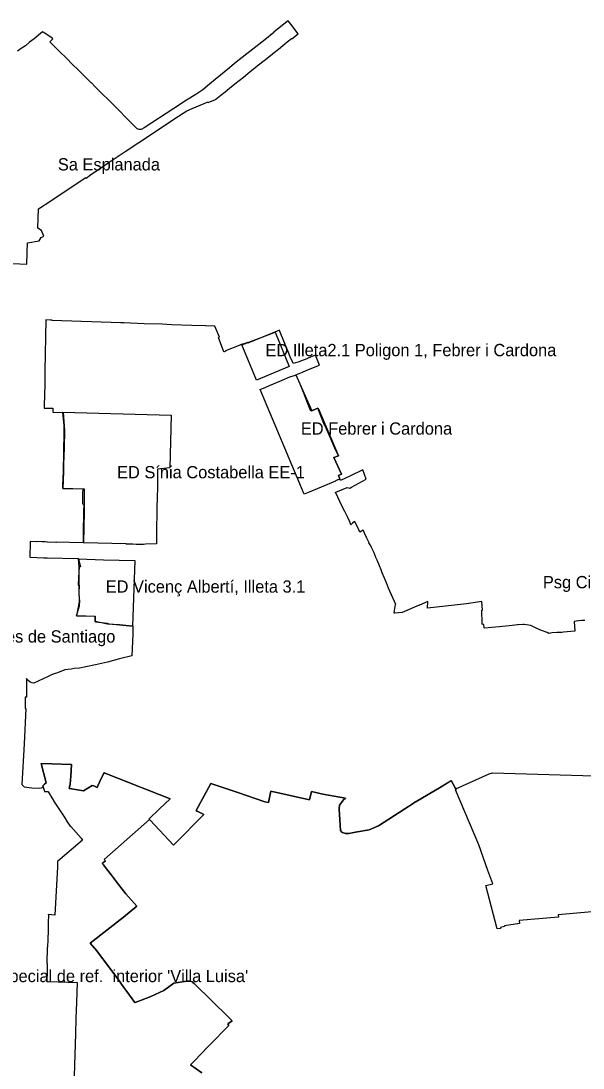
# Model space of a CAD drawing. Extents: x 599912 to 613490, y 4411003 to 4422920.
# Drawn here: x 607718 to 608268, y 4415128 to 4416152 of the extents above; entities that cross this region are included whole.
import ezdxf

# ---------------------------------------------------------------- set-up
doc = ezdxf.new("R2010")
doc.units = 0
for name, color, linetype in [('Estudi de Detall', 7, 'Continuous'), ('Límit sòl urbanitzable', 7, 'Continuous'), ('Pla Especial de Reforma Interior', 7, 'Continuous'), ('Sector amb disposicions transitòries', 7, 'Continuous'), ("Unitat d'Actuació", 7, 'Continuous'), ("Àrea d'interès Social", 7, 'Continuous')]:
    doc.layers.add(name, color=color, linetype=linetype)

msp = doc.modelspace()

# ---------------------------------------------------------------- linework, layer by layer
at = {"layer": 'Estudi de Detall'}
for points in [[(607966.5, 4415847.7), (607980, 4415814.3), (607948.2, 4415801), (607945.9, 4415806.4), (607936.5, 4415829.1), (607933.8, 4415835.4)], [(607986.7, 4415806), (608002.2, 4415770.9), (608007.2, 4415773), (608008.2, 4415773.4), (608008.2, 4415773.4), (608008.5, 4415773.5), (608028.2, 4415726.8), (608023.7, 4415725.4), (608031.2, 4415708.9), (608028.2, 4415707.5), (608029.7, 4415704.2), (608028.7, 4415703.7), (608026.1, 4415702.6), (608025.3, 4415702.3), (608025.4, 4415702.1), (608011.5, 4415696.2), (607999.6, 4415691.3), (607994.9, 4415689.3), (607951.8, 4415791.7), (607957.3, 4415794.1), (607960.8, 4415795.5), (607964.7, 4415797.2), (607968.6, 4415798.8), (607973.1, 4415800.7), (607980.9, 4415804), (607986.4, 4415805.8)], [(607758.6, 4415769.6), (607864.8, 4415766.8), (607863.3, 4415715.3), (607851.4, 4415713.9), (607851.2, 4415695.9), (607850.6, 4415676.5), (607850.5, 4415672.3), (607850.7, 4415669.4), (607850.4, 4415657.1), (607850.4, 4415656.9), (607850.2, 4415641), (607839.6, 4415640.4), (607837.6, 4415640.3), (607833.1, 4415640.3), (607830.3, 4415640.3), (607827.2, 4415640.4), (607820.5, 4415640.5), (607820.6, 4415640.7), (607778.8, 4415641.8), (607779, 4415651.5), (607779.3, 4415671.5), (607779.3, 4415672.5), (607779.4, 4415679.4), (607778.1, 4415679.5), (607778.1, 4415680.7), (607778.3, 4415686.4), (607778.4, 4415689.9), (607778.6, 4415694.3), (607779.6, 4415694.3), (607779.5, 4415694.3), (607778.6, 4415694.4), (607778.6, 4415694.3), (607758.6, 4415695.1), (607758.7, 4415695.1), (607758.7, 4415695.1), (607758.8, 4415698.5), (607759.2, 4415711.6), (607759.2, 4415711.7), (607759.4, 4415718.4), (607759.4, 4415718.4), (607759.4, 4415718.4), (607759.5, 4415723.5), (607759.5, 4415723.5), (607759.9, 4415757), (607759.8, 4415759.4), (607759.1, 4415766.3), (607758.9, 4415766.2), (607758.6, 4415769), (607758.6, 4415769.2)], [(607774.1, 4415626.1), (607798.6, 4415625.3), (607829.2, 4415624.4), (607826.7, 4415560.2), (607814.1, 4415561.5), (607802.4, 4415562.4), (607790.2, 4415564.8), (607790.3, 4415569.7), (607771.9, 4415570.5), (607775.1, 4415580.2), (607774.6, 4415600.5), (607774.5, 4415618.5)]]:
    msp.add_lwpolyline(points, close=True, dxfattribs=at)
at = {"layer": 'Límit sòl urbanitzable'}
msp.add_lwpolyline([(607894.7, 4415123.5), (607883.5, 4415131.4), (607885.7, 4415133.6), (607888.8, 4415136.8), (607892.6, 4415140.8), (607901.8, 4415150.2), (607921.2, 4415169.8), (607920, 4415171.4), (607924.2, 4415174.5), (607920.7, 4415178), (607887.7, 4415210.4), (607887.2, 4415210.8), (607885.9, 4415212.1), (607885.7, 4415212.3), (607885.5, 4415212.5), (607883.2, 4415213.2), (607879.8, 4415213.4), (607867.3, 4415211.2), (607857.6, 4415204.2), (607844.6, 4415198.1), (607834.5, 4415194.3), (607829.3, 4415192.4), (607829.2, 4415192.4), (607829.1, 4415192.3), (607821.2, 4415203), (607818.5, 4415207), (607812.6, 4415215.5), (607798.4, 4415234.2), (607791.8, 4415242.9), (607785.4, 4415250.4), (607817.9, 4415275.8), (607831.1, 4415286.7), (607820.2, 4415298.7), (607813.2, 4415307.8), (607806.2, 4415316.9), (607801.4, 4415323), (607798.5, 4415326.9), (607798.2, 4415327.2), (607797.2, 4415328.2), (607800.5, 4415330.9), (607799.2, 4415332.2), (607843.5, 4415371.3), (607843.5, 4415371.3), (607843, 4415371.9), (607853.4, 4415381.8), (607863.6, 4415391.6), (607842.3, 4415399.9), (607836.4, 4415402.2), (607834.8, 4415402.9), (607799.1, 4415416.9), (607798.6, 4415416.1), (607797.4, 4415413.8), (607796.2, 4415411.5), (607792.9, 4415404.3), (607792.4, 4415402.7), (607791, 4415403.3), (607789.6, 4415403.8), (607788.7, 4415404.1), (607787.5, 4415404.6), (607778.8, 4415399.5), (607765.2, 4415401.5), (607765.2, 4415401.6), (607764.9, 4415401.7), (607766, 4415405.9), (607766.4, 4415413.8), (607767, 4415425), (607767, 4415425.1), (607747.8, 4415425.8), (607737.5, 4415426.2), (607742, 4415408.5), (607742.4, 4415407.1), (607742.3, 4415407.1), (607740.7, 4415405.7), (607739, 4415404.3), (607739.3, 4415403.3), (607739.4, 4415402.9), (607740.7, 4415398.9), (607740.8, 4415398.7), (607744, 4415398.6), (607744.3, 4415398.5), (607746.6, 4415394.7), (607746.9, 4415394.1), (607749.4, 4415390), (607749.6, 4415389.7), (607760.6, 4415373), (607760.6, 4415373), (607762.8, 4415369), (607766, 4415364.9), (607766.4, 4415364.5), (607776.5, 4415353), (607778, 4415351), (607753.6, 4415330.4), (607753.6, 4415329.9), (607753.4, 4415325), (607750.9, 4415277.8), (607744.3, 4415278.3), (607744.3, 4415278.1), (607744.6, 4415278.1), (607744.6, 4415278.1), (607744.4, 4415270.2), (607744.2, 4415262.6), (607744, 4415254.4), (607743.8, 4415246.5), (607743.5, 4415246.5), (607743, 4415230.6), (607743.4, 4415230.6), (607743.2, 4415222.7), (607742.9, 4415213), (607754.2, 4415212.7), (607772.6, 4415212.1), (607772.6, 4415211.9), (607772, 4415192.8), (607771.5, 4415176.6), (607771, 4415161.6), (607769.1, 4415100.2)], dxfattribs=at)
at = {"layer": 'Pla Especial de Reforma Interior'}
msp.add_lwpolyline([(607702.9, 4415915.1), (607723.5, 4415914.3), (607723.9, 4415925.7), (607724.1, 4415935), (607735.5, 4415937.2), (607737.6, 4415940.4), (607740.1, 4415941.7), (607737.7, 4415947.3), (607734.2, 4415949.6), (607734.8, 4415968.5), (607746.9, 4415976.3), (607776.6, 4415996), (607781.1, 4415999), (607781.5, 4415998.5), (607785.7, 4416001.5), (607799.6, 4416011.1), (607801.9, 4416012.6), (607811, 4416018.7), (607819.7, 4416024.6), (607846.3, 4416042.1), (607868.4, 4416056.7), (607879.9, 4416064.3), (607885.3, 4416066.6), (607900.8, 4416072.9), (607900.9, 4416072.5), (607908, 4416075.2), (607908.4, 4416075.5), (607913.2, 4416079.4), (607917.4, 4416082.7), (607921.7, 4416086.2), (607927.1, 4416090.5), (607931.1, 4416093.7), (607935.4, 4416097.2), (607939.7, 4416100.6), (607942.1, 4416102.6), (607944.9, 4416104.8), (607948.9, 4416108.1), (607957, 4416114.5), (607965.4, 4416121.3), (607969.5, 4416124.6), (607973.8, 4416128.1), (607978.2, 4416131.6), (607982.4, 4416135), (607982.7, 4416134.7), (607988.9, 4416139.4), (607981.7, 4416149), (607979.1, 4416152.1), (607973.6, 4416147.9), (607965, 4416141), (607965.1, 4416140.9), (607956.3, 4416133.7), (607947.5, 4416126.8), (607938.8, 4416120), (607926.6, 4416110.4), (607921.6, 4416106.4), (607907.7, 4416094.7), (607902.1, 4416090.3), (607895.7, 4416084.7), (607888.7, 4416080.2), (607879.7, 4416074.7), (607867.1, 4416066.5), (607838.2, 4416047.6), (607836.1, 4416046.3), (607835.2, 4416046), (607834.3, 4416045.9), (607833.3, 4416046), (607832.4, 4416046.2), (607831.5, 4416046.5), (607824.6, 4416053.5), (607809.8, 4416068.3), (607809.8, 4416068.3), (607790.5, 4416087.4), (607790.5, 4416087.4), (607786.4, 4416091.8), (607786.3, 4416091.7), (607780.8, 4416097.2), (607774.6, 4416103.3), (607767.2, 4416110.6), (607763.2, 4416114.6), (607754.4, 4416123.3), (607746.1, 4416131.5), (607748.9, 4416134.6), (607748.2, 4416135.3), (607740.2, 4416140.9), (607738.9, 4416141.3), (607730.7, 4416134.7), (607726.2, 4416131.2), (607722.1, 4416127.9), (607717.9, 4416125), (607714.4, 4416122.5)], dxfattribs=at)
at = {"layer": 'Sector amb disposicions transitòries'}
msp.add_lwpolyline([(608269.5, 4415566), (608266.3, 4415565.8), (608263, 4415565.4), (608261, 4415565.2), (608260.9, 4415565.1), (608258.8, 4415564.8), (608259.7, 4415555.5), (608259.3, 4415555.5), (608248.6, 4415554.5), (608247, 4415554.3), (608244.3, 4415554.1), (608242, 4415554), (608237.3, 4415553.9), (608235.6, 4415553.6), (608235.4, 4415553.5), (608234, 4415553.3), (608232.4, 4415554), (608227.1, 4415556), (608221.8, 4415558.4), (608216.4, 4415560.9), (608210.1, 4415562.1), (608210.1, 4415562.1), (608210, 4415562.1), (608208.6, 4415562), (608204.1, 4415561.5), (608203.5, 4415561.5), (608198.4, 4415561), (608195.4, 4415560.7), (608192, 4415560.3), (608185.6, 4415559.7), (608178.4, 4415559), (608171.3, 4415558.4), (608171.3, 4415558.4), (608171.3, 4415558.4), (608171.2, 4415558.8), (608171.2, 4415558.8), (608171, 4415558.8), (608171, 4415558.8), (608170.6, 4415562.1), (608170, 4415562.1), (608170, 4415562.1), (608168.8, 4415562.2), (608168.8, 4415563), (608168.7, 4415575.9), (608168.7, 4415575.9), (608168.7, 4415575.9), (608168.8, 4415576), (608169.2, 4415576.1), (608168.5, 4415584.3), (608153.5, 4415582.2), (608115.5, 4415578), (608115.7, 4415584.5), (608107.7, 4415580.8), (608107.3, 4415580.7), (608107.2, 4415581), (608090.5, 4415573.6), (608083.4, 4415573.2), (608082.9, 4415573.1), (608083.3, 4415575.7), (608083, 4415575.8), (608084, 4415581.4), (608084.4, 4415581.5), (608077.4, 4415597.6), (608075.2, 4415602.8), (608073.3, 4415607.3), (608071.2, 4415612.5), (608070.1, 4415615.3), (608068.5, 4415619.2), (608066.1, 4415624.9), (608065, 4415627.4), (608063.2, 4415632.1), (608060.5, 4415637.3), (608059.5, 4415639.4), (608059.2, 4415639.8), (608058.1, 4415641.7), (608058.4, 4415641.8), (608056.1, 4415646.5), (608053.8, 4415651.2), (608052.7, 4415653.8), (608052.5, 4415654.1), (608049.2, 4415652.4), (608048.3, 4415654.5), (608045.6, 4415660.1), (608044.3, 4415662.2), (608044.1, 4415662.7), (608044, 4415662.6), (608042.1, 4415660.9), (608040.9, 4415659.9), (608040.5, 4415659.5), (608039.5, 4415662.3), (608037.4, 4415666.7), (608034.6, 4415672.5), (608032.1, 4415677.4), (608025.5, 4415691.2), (608025.8, 4415691.4), (608036.7, 4415695.9), (608039.4, 4415695.3), (608041.2, 4415696.3), (608055.4, 4415704), (608052.1, 4415713.1), (608040, 4415707.3), (608030.4, 4415702.8), (608028.2, 4415707.5), (608031.2, 4415708.9), (608023.7, 4415725.4), (608028.2, 4415726.8), (608025.9, 4415732.1), (608021.9, 4415741.3), (608015.1, 4415757), (608014.7, 4415756.8), (608008.2, 4415773.4), (608001.4, 4415770.6), (607999.4, 4415775.5), (607997.4, 4415780.3), (607995.4, 4415785.4), (607994.3, 4415788.2), (607993.4, 4415790.4), (607992.4, 4415793), (607991.4, 4415795.4), (607989.1, 4415800.7), (607986.7, 4415806), (607993.1, 4415808.7), (607996.6, 4415810.2), (607997.3, 4415810.5), (608009.9, 4415815.6), (608005.8, 4415825.2), (608001, 4415823.2), (607995.9, 4415821.2), (607991.2, 4415819.5), (607990, 4415818.9), (607988.5, 4415818.4), (607984, 4415817), (607982.9, 4415819.7), (607981.8, 4415822.2), (607978.8, 4415829.5), (607975.5, 4415837.4), (607970.7, 4415849.4), (607970.6, 4415849.7), (607968.3, 4415848.8), (607939.7, 4415837), (607939.4, 4415837.6), (607935.3, 4415835.9), (607935, 4415836.4), (607933.5, 4415835.8), (607933.1, 4415835.7), (607931.3, 4415834.9), (607917.8, 4415829.6), (607918, 4415829.2), (607916.5, 4415828.6), (607916.2, 4415828.5), (607910.9, 4415842.6), (607911.2, 4415842.7), (607911.9, 4415843), (607908.4, 4415851.5), (607907.3, 4415853.7), (607898.5, 4415854), (607898.4, 4415854), (607884.9, 4415854.3), (607865.1, 4415855.1), (607855.8, 4415855.5), (607838.1, 4415856.1), (607818.4, 4415856.8), (607815.3, 4415856.9), (607748.1, 4415859.2), (607748.1, 4415859.4), (607748, 4415859.4), (607746.6, 4415859.4), (607742.1, 4415859.7), (607741.2, 4415809.5), (607740.9, 4415794.4), (607740.8, 4415788.9), (607740.5, 4415773.6), (607746.8, 4415773.6), (607749, 4415773.6), (607748.9, 4415770.8), (607748.9, 4415769.5), (607759.1, 4415769.2), (607760.3, 4415751.8), (607759.9, 4415734.6), (607759.4, 4415718.4), (607759.4, 4415718.4), (607759.4, 4415718.4), (607759.2, 4415711.6), (607758.7, 4415695.1), (607778.5, 4415694.5), (607779.4, 4415694.5), (607779.4, 4415694.4), (607779.5, 4415694.4), (607779.4, 4415679.7), (607779.4, 4415672.4), (607778.8, 4415641.7), (607778.7, 4415641.7), (607778.7, 4415641.7), (607752, 4415642.5), (607751.9, 4415642.3), (607743.7, 4415642.5), (607743.2, 4415642.5), (607741.3, 4415642.7), (607738.5, 4415642.8), (607733.9, 4415643), (607732.9, 4415642.7), (607726.7, 4415643.2), (607726.7, 4415642.1), (607726.7, 4415642), (607726.4, 4415627.7), (607740, 4415627.3), (607742.5, 4415627.1), (607743.3, 4415627.1), (607773.8, 4415626.5), (607773.9, 4415626.2), (607774.3, 4415624.8), (607776, 4415618.5), (607774.5, 4415618.5), (607774, 4415607.6), (607773.7, 4415600.6), (607774, 4415600.5), (607774.6, 4415600.5), (607774.6, 4415600.2), (607774.4, 4415593), (607774.3, 4415590), (607774.6, 4415590.1), (607774.7, 4415590.1), (607774.7, 4415589.7), (607774.9, 4415583.3), (607774.2, 4415583.3), (607774, 4415580.5), (607772.9, 4415575.7), (607771.9, 4415570.5), (607772.3, 4415570.5), (607790.3, 4415570), (607790.3, 4415569.7), (607790.2, 4415564.8), (607790.5, 4415564.7), (607802.4, 4415563.2), (607802.4, 4415562.9), (607802.4, 4415562.7), (607802.9, 4415562.7), (607802.9, 4415562.5), (607803.9, 4415562.5), (607814.1, 4415561.5), (607827, 4415560.2), (607827.1, 4415552.4), (607826.2, 4415531.4), (607814.2, 4415528.3), (607802.3, 4415525.1), (607790.5, 4415522.6), (607781.2, 4415520.7), (607775, 4415519.3), (607769.9, 4415518.8), (607766.7, 4415518.4), (607760.6, 4415517.7), (607753.5, 4415514.8), (607751.3, 4415514.2), (607749.1, 4415513.5), (607746.8, 4415512.5), (607743.7, 4415510.9), (607735.3, 4415507), (607734.7, 4415506.7), (607730.3, 4415504.6), (607728.7, 4415504.8), (607726.7, 4415505.7), (607724.3, 4415507.4), (607723.6, 4415508.2), (607723.2, 4415509.3), (607723.2, 4415502.5), (607723.1, 4415490.8), (607721.8, 4415490.8), (607721.8, 4415479.9), (607722.6, 4415479.8), (607720.7, 4415445.4), (607718.5, 4415405.5), (607720.8, 4415403.1), (607728.2, 4415402.3), (607735.5, 4415402.1), (607737.7, 4415402.2), (607739.3, 4415402.9), (607739.4, 4415402.9), (607739.3, 4415403.3), (607739, 4415404.3), (607740.7, 4415405.7), (607742.3, 4415407.1), (607742.4, 4415407.1), (607742, 4415408.5), (607737.5, 4415426.2), (607747.8, 4415425.8), (607767, 4415425.1), (607767, 4415425), (607766.4, 4415413.8), (607766, 4415405.9), (607764.9, 4415401.7), (607765.2, 4415401.6), (607765.2, 4415401.5), (607778.8, 4415399.5), (607787.5, 4415404.6), (607788.7, 4415404.1), (607789.6, 4415403.8), (607791, 4415403.3), (607792.4, 4415402.7), (607792.9, 4415404.3), (607796.2, 4415411.5), (607797.4, 4415413.8), (607798.6, 4415416.1), (607799.1, 4415416.9), (607834.8, 4415402.9), (607836.4, 4415402.2), (607842.3, 4415399.9), (607863.6, 4415391.6), (607853.4, 4415381.8), (607843, 4415371.9), (607843.5, 4415371.3), (607843.8, 4415371.1), (607844, 4415370.8), (607866.8, 4415346.2), (607866.9, 4415346.2), (607866.9, 4415346.3), (607866.9, 4415346.3), (607879.5, 4415359), (607885.2, 4415364.7), (607896.4, 4415376), (607896.4, 4415376.1), (607896.5, 4415376.1), (607890, 4415379.4), (607889.6, 4415379.6), (607889.3, 4415379.8), (607889, 4415380), (607903.6, 4415406.6), (607929.9, 4415397.6), (607956.3, 4415388.6), (607959.9, 4415387.9), (607962.3, 4415399), (607999.9, 4415390.6), (608001.8, 4415398.8), (608012.9, 4415396.2), (608035.2, 4415392.2), (608035.1, 4415392.1), (608035.1, 4415392), (608034.9, 4415391.9), (608033.2, 4415390.4), (608029.2, 4415385.4), (608028.9, 4415381.6), (608029.5, 4415371.1), (608030.2, 4415360.5), (608032, 4415358.7), (608032.2, 4415358.6), (608032.2, 4415358.6), (608032.3, 4415358.6), (608035.2, 4415357.5), (608038.4, 4415357.6), (608046.7, 4415359.1), (608046.9, 4415359.2), (608058.3, 4415361.2), (608058.4, 4415361.3), (608067.6, 4415365.1), (608093.3, 4415381.8), (608101.5, 4415387.1), (608103, 4415388.1), (608103.5, 4415388.3), (608128.7, 4415403.3), (608138.5, 4415409.3), (608142.5, 4415402.3), (608143.1, 4415401.2), (608143.2, 4415401.2), (608175.8, 4415415.8), (608179.1, 4415417), (608289.6, 4415413.8)], dxfattribs=at)
at = {"layer": "Àrea d'interès Social"}
msp.add_lwpolyline([(608290.9, 4415282.4), (608243.4, 4415278.2), (608243.6, 4415275.8), (608205, 4415272.7), (608205.5, 4415269.5), (608190.9, 4415267.5), (608190.9, 4415266.7), (608186.7, 4415265.8), (608186.9, 4415264.8), (608183.6, 4415264.4), (608172.6, 4415306.9), (608179.3, 4415308.4), (608174.5, 4415321.6), (608165.5, 4415346.5), (608142.8, 4415400.2), (608143.8, 4415400.8), (608143.6, 4415400.7), (608143.2, 4415401.2), (608143.1, 4415401.2), (608142.5, 4415402.3), (608138.5, 4415409.3), (608137.8, 4415408.7), (608128.7, 4415403.3), (608103.5, 4415388.3), (608103, 4415388.1), (608101.5, 4415387.1), (608093.3, 4415381.8), (608067.6, 4415365.1), (608058.4, 4415361.3), (608058.3, 4415361.2), (608046.9, 4415359.2), (608046.7, 4415359.1), (608038.4, 4415357.6), (608035.2, 4415357.5), (608032.3, 4415358.6), (608032.2, 4415358.6), (608032.2, 4415358.6), (608032, 4415358.7), (608030.2, 4415360.5), (608029.5, 4415371.1), (608028.9, 4415381.6), (608029.2, 4415385.4), (608033.2, 4415390.4), (608034.9, 4415391.9), (608035.1, 4415392), (608035.1, 4415392.1), (608035.2, 4415392.2), (608012.9, 4415396.2), (608001.8, 4415398.8), (607999.9, 4415390.6), (607962.3, 4415399), (607959.9, 4415387.9), (607956.3, 4415388.6), (607929.9, 4415397.6), (607903.6, 4415406.6), (607889, 4415380), (607889.3, 4415379.8), (607889.6, 4415379.6), (607890, 4415379.4), (607896.5, 4415376.1), (607896.4, 4415376.1), (607896.4, 4415376), (607885.2, 4415364.7), (607879.5, 4415359), (607866.9, 4415346.3), (607866.9, 4415346.3), (607866.9, 4415346.2), (607866.8, 4415346.2), (607844, 4415370.8), (607843.8, 4415371.1), (607843.5, 4415371.3), (607843.5, 4415371.3), (607799.2, 4415332.2), (607800.5, 4415330.9), (607797.2, 4415328.2), (607798.2, 4415327.2), (607798.5, 4415326.9), (607801.4, 4415323), (607806.2, 4415316.9), (607813.2, 4415307.8), (607820.2, 4415298.7), (607831.1, 4415286.7), (607817.9, 4415275.8), (607785.4, 4415250.4), (607791.8, 4415242.9), (607798.4, 4415234.2), (607812.6, 4415215.5), (607818.5, 4415207), (607821.2, 4415203), (607829.1, 4415192.3), (607829.2, 4415192.4), (607829.3, 4415192.4), (607834.5, 4415194.3), (607844.6, 4415198.1), (607857.6, 4415204.2), (607867.3, 4415211.2), (607879.8, 4415213.4), (607883.2, 4415213.2), (607885.5, 4415212.5), (607885.7, 4415212.3), (607885.9, 4415212.1), (607887.2, 4415210.8), (607887.7, 4415210.4), (607920.7, 4415178), (607924.2, 4415174.5), (607920, 4415171.4), (607921.2, 4415169.8), (607901.8, 4415150.2), (607892.6, 4415140.8), (607888.8, 4415136.8), (607885.7, 4415133.6), (607883.5, 4415131.4), (607894.7, 4415123.5)], dxfattribs=at)

# ---------------------------------------------------------------- texts
at = {"layer": 'Estudi de Detall'}
for s, p in [('ED Illeta2.1 Poligon 1, Febrer i Cardona', (607956.9, 4415824.3)), ('ED Febrer i Cardona', (607991.5, 4415747.6)), ('ED Sínia Costabella EE-1', (607811.7, 4415704.9)), ('ED Vicenç Albertí, Illeta 3.1', (607800.6, 4415593.1))]:
    msp.add_text(s, height=12, dxfattribs=at).set_placement(p)
at = {"layer": 'Pla Especial de Reforma Interior'}
msp.add_text('Sa Esplanada', height=12, dxfattribs=at).set_placement((607753.8, 4416005.9))
at = {"layer": 'Sector amb disposicions transitòries'}
for s, p in [('Psg Circumval -Sinia Costabella', (608228.3, 4415597.4)), ("Pla especial de ref.  interior 'Villa Luisa'", (607661.8, 4415212.3))]:
    msp.add_text(s, height=12, dxfattribs=at).set_placement(p)
at = {"layer": "Unitat d'Actuació"}
msp.add_text('Casernes de Santiago', height=12, dxfattribs=at).set_placement((607651.3, 4415544.3))

doc.saveas('drawing.dxf')
